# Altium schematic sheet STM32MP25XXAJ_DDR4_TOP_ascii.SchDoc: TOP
size A4; Date: Not used; ApprovedBy: Not used; CheckedBy: Not used; Author: Not used; CompanyName: STMicroelectronics; DrawnBy: Not used; Engineer: Not used; Organization: Not used; Address1: Not used; Address2: Not used; Address3: Not used; Address4: Not used; DocumentNumber: 2; Revision: Not used; SheetNumber: 2; SheetTotal: 7
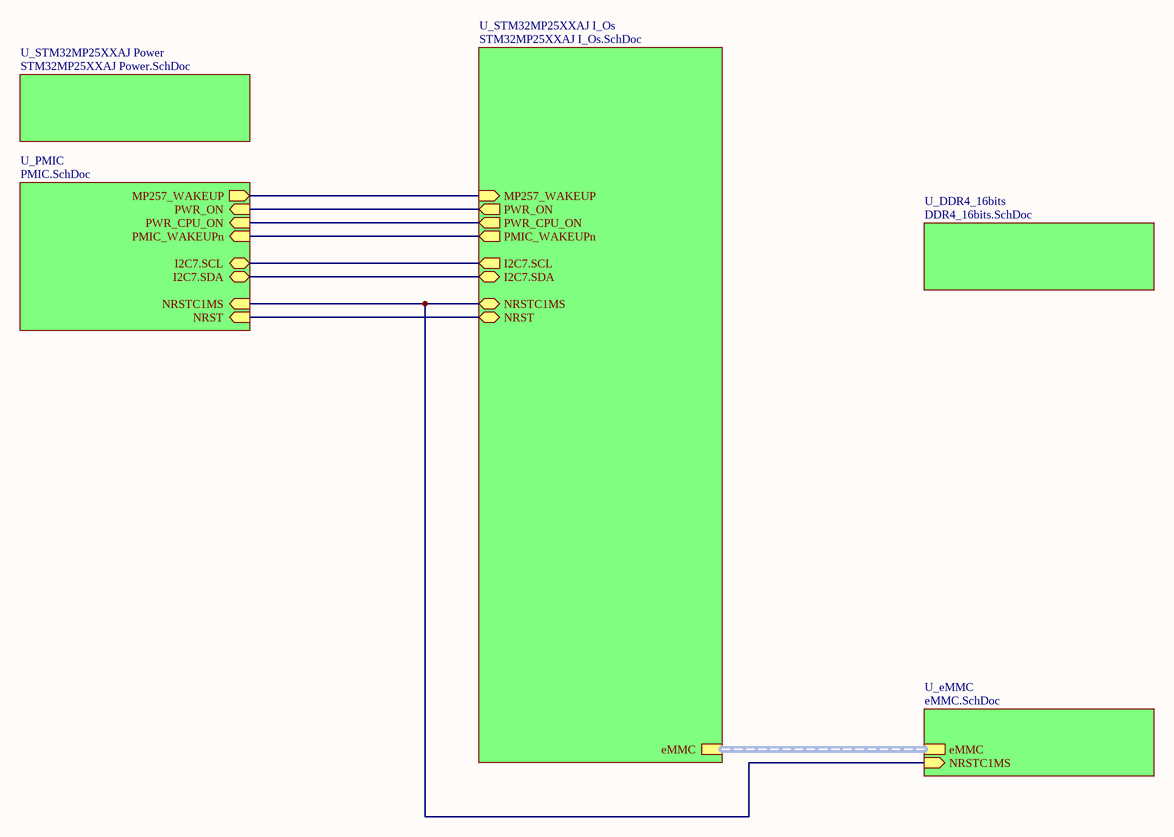
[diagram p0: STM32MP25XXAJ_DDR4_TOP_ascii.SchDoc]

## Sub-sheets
U_DDR4_16bits = DDR4_16bits.SchDoc: no entries
U_eMMC = eMMC.SchDoc: eMMC (harness eMMC), NRSTC1MS (in)
U_PMIC = PMIC.SchDoc: PMIC_WAKEUPn (in), NRST (in), I2C7.SCL (bidir), PWR_ON (in), PWR_CPU_ON (in), NRSTC1MS (in), I2C7.SDA (bidir), MP257_WAKEUP (out)
U_STM32MP25XXAJ I_Os = STM32MP25XXAJ I_Os.SchDoc: NRST (bidir), PWR_ON (out), NRSTC1MS (bidir), I2C7.SDA (bidir), I2C7.SCL (out), PWR_CPU_ON (out), MP257_WAKEUP (in), PMIC_WAKEUPn (out), eMMC (harness eMMC)
U_STM32MP25XXAJ Power = STM32MP25XXAJ Power.SchDoc: no entries

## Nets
(unnamed): sheet U_STM32MP25XXAJ I_Os/NRST, sheet U_PMIC/NRST
(unnamed): sheet U_STM32MP25XXAJ I_Os/PWR_ON, sheet U_PMIC/PWR_ON  [a separate net that carries the same name]
(unnamed): sheet U_STM32MP25XXAJ I_Os/NRSTC1MS, sheet U_PMIC/NRSTC1MS, sheet U_eMMC/NRSTC1MS  [a separate net that carries the same name]
(unnamed): sheet U_STM32MP25XXAJ I_Os/I2C7.SDA, sheet U_PMIC/I2C7.SDA  [a separate net that carries the same name]
(unnamed): sheet U_STM32MP25XXAJ I_Os/I2C7.SCL, sheet U_PMIC/I2C7.SCL  [a separate net that carries the same name]
(unnamed): sheet U_STM32MP25XXAJ I_Os/PWR_CPU_ON, sheet U_PMIC/PWR_CPU_ON  [a separate net that carries the same name]
(unnamed): sheet U_STM32MP25XXAJ I_Os/MP257_WAKEUP, sheet U_PMIC/MP257_WAKEUP  [a separate net that carries the same name]
(unnamed): sheet U_STM32MP25XXAJ I_Os/PMIC_WAKEUPn, sheet U_PMIC/PMIC_WAKEUPn  [a separate net that carries the same name]

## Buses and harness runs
harness sheet U_eMMC/eMMC = sheet U_STM32MP25XXAJ I_Os/eMMC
